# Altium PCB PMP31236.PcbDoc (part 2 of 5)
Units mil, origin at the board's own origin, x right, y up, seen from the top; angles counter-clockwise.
Board outline 6425 x 5322.16 mil, 6 copper layers (Top Layer, Power / GND 1, Signal Layer 1, Signal Layer 2, Power / GND 2, Bottom Layer), stack 78.712 mil thick; 732 components, 346 nets, 1735 pads, 719 vias.
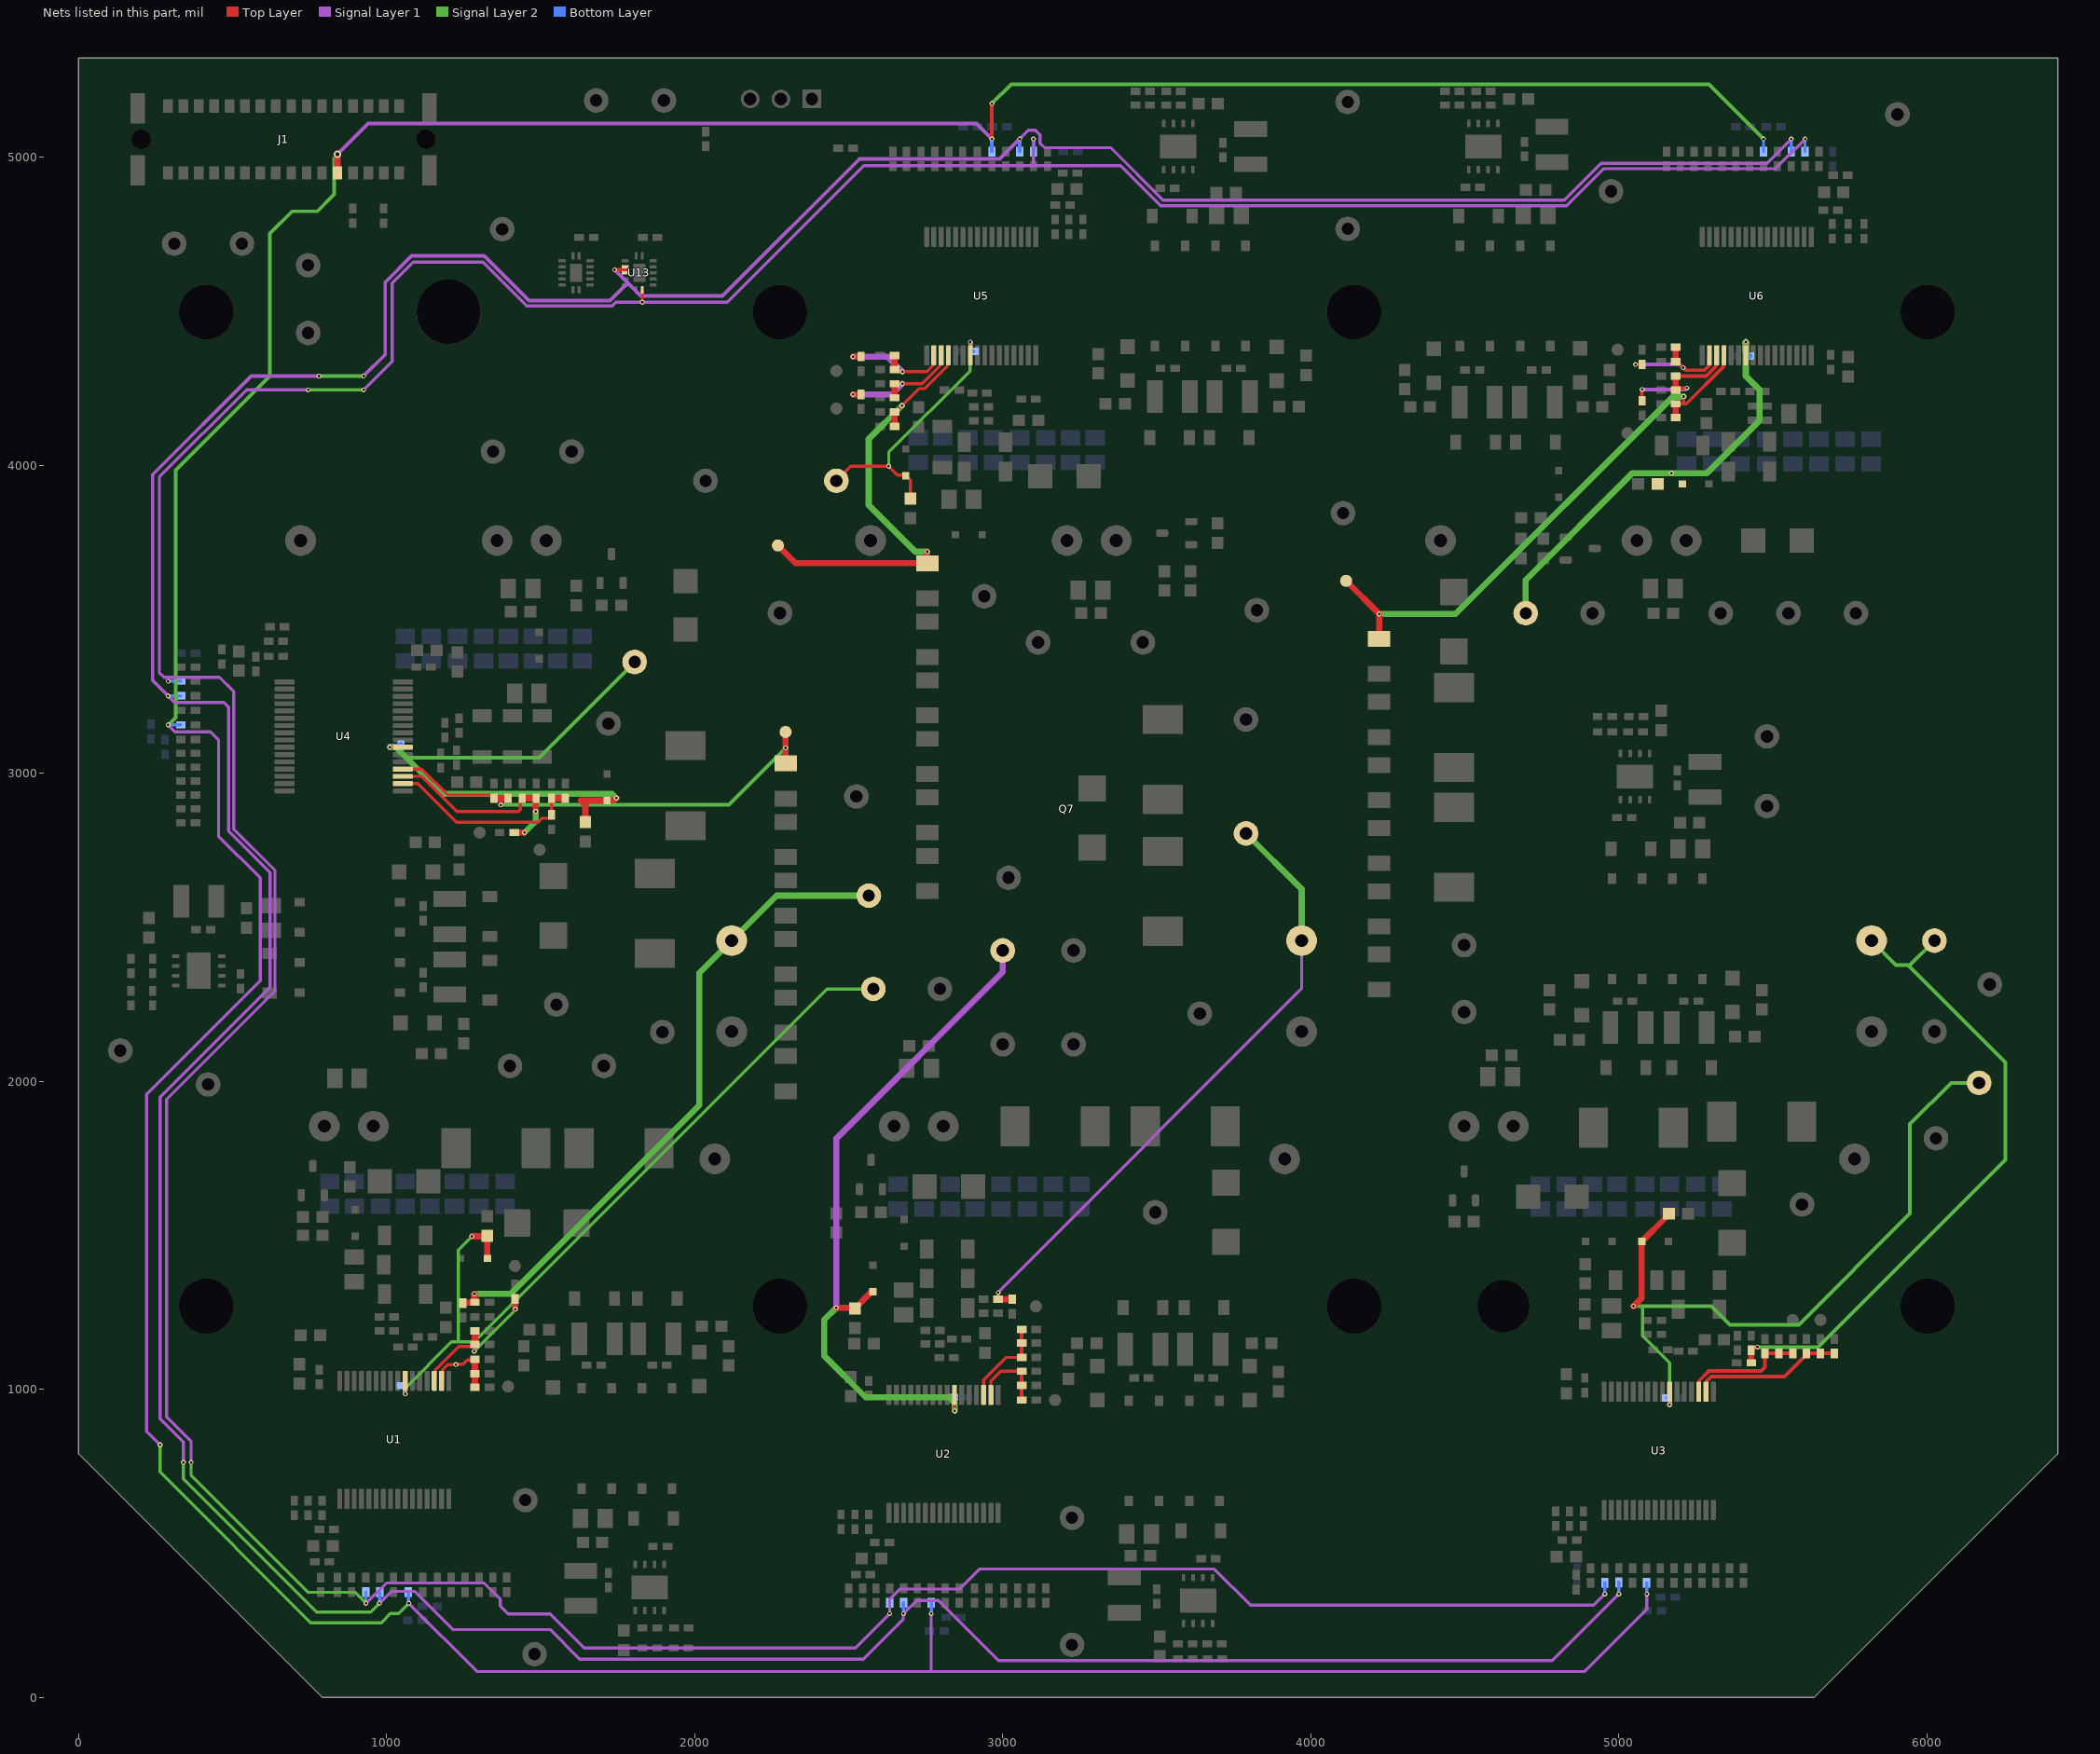
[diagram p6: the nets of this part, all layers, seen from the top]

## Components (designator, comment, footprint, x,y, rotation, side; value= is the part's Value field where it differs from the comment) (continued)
R248 "CRCW0402154KFKED" 0402 1887.81,489.9 r0 top value=154k
R249 "CRCW04020000Z0ED" 0402 1854.47,225 r180 top value=0
R250 "CRCW040215K4FKED" 0402 1955,160 r180 top value=15.4k
R251 "CRCW040212K1FKED" 0402 1956.38,225 r180 top value=12.1k
R252 "CRCW060310R0FKEAHP" 0603 1125,2776.38 r0 top value=10.0
R253 "CRCW08054K70JNEA" 0805_HV 625,2530 r90 top value=4.7k
R254 "CRCW040266K5FKED" 0402 170,2374.37 r90 top value=66.5k
R255 "CRCW060310R0FKEAHP" 0603 1145,2090 r0 top value=10.0
R256 "CRCW0402154KFKED" 0402 525,2325 r270 top value=154k
R257 "CRCW04020000Z0ED" 0402 240,2374.37 r90 top value=0
R258 "CRCW040215K4FKED" 0402 170,2270 r90 top value=15.4k
R259 "CRCW040212K1FKED" 0402 240,2270 r90 top value=12.1k
R260 "CRCW060310R0FKEAHP" 0603 3213.05,1065.12 r90 top value=10.0
R261 "CRCW08054K70JNEA" 0805_HV 3442.3,530.12 r180 top value=4.7k
R262 "CRCW040266K5FKED" 0402 3592.87,125 r180 top value=66.5k
R263 "CRCW060310R0FKEAHP" 0603 3895,1025 r90 top value=10.0
R264 "CRCW0402154KFKED" 0402 3668.38,449.91 r0 top value=154k
R265 "CRCW04020000Z0ED" 0402 3592.87,173.74 r180 top value=0
R266 "CRCW040215K4FKED" 0402 3688.62,125 r180 top value=15.4k
R267 "CRCW040212K1FKED" 0402 3688.05,173.74 r180 top value=12.1k
R268 "CRCW060310R0FKEAHP" 0603 3985,4325 r270 top value=10.0
R269 "CRCW08054K70JNEA" 0805_HV 3735,4815 r0 top value=4.7k
R270 "CRCW040266K5FKED" 0402 3554.25,5215 r0 top value=66.5k
R271 "CRCW060310R0FKEAHP" 0603 3310,4330 r270 top value=10.0
R272 "CRCW0402154KFKED" 0402 3535,4900 r180 top value=154k
R273 "CRCW04020000Z0ED" 0402 3554.25,5170 r0 top value=0
R274 "CRCW040215K4FKED" 0402 3455,5215 r0 top value=15.4k
R275 "CRCW040212K1FKED" 0402 3455,5170 r0 top value=12.1k
R276 "CRCW060310R0FKEAHP" 0603 5465,2265 r270 top value=10.0
R277 "CRCW08054K70JNEA" 0805_HV 5232.01,2755 r0 top value=4.7k
R278 "CRCW040266K5FKED" 0402 5056.38,3185 r0 top value=66.5k
R279 "CRCW060310R0FKEAHP" 0603 4775,2265 r270 top value=10.0
R280 "CRCW0402154KFKED" 0402 5018.33,2856.32 r180 top value=154k
R281 "CRCW04020000Z0ED" 0402 5054.72,3135 r0 top value=0
R282 "CRCW040215K4FKED" 0402 4955,3185 r0 top value=15.4k
R283 "CRCW040212K1FKED" 0402 4955,3135 r0 top value=12.1k
R284 "CRCW060310R0FKEAHP" 0603 4970,4278.5 r270 top value=10.0
R285 "CRCW08054K70JNEA" 0805_HV 4730,4815 r0 top value=4.7k
R286 "CRCW040266K5FKED" 0402 4560.28,5215 r0 top value=66.5k
R287 "CRCW060310R0FKEAHP" 0603 4305,4278.5 r270 top value=10.0
R288 "CRCW0402154KFKED" 0402 4525.53,4903.34 r180 top value=154k
R289 "CRCW04020000Z0ED" 0402 4560.28,5170 r0 top value=0
R290 "CRCW040215K4FKED" 0402 4459.19,5215 r0 top value=15.4k
R291 "CRCW040212K1FKED" 0402 4459.19,5170 r0 top value=12.1k
R292 "CRCW040210K0FKED" 0402 2490,5030 r0 top value=10.0k
R293 "CRCW040210K0FKED" 0402 2035,5060 r90 top value=10.0k
R294 "CRCW040247K0JNED" 0402 889.84,4810 r270 top value=47k
R295 "CRCW040247K0JNED" 0402 990,4810 r90 top value=47k
T1 "YA8916-BL" Coilcraft_YA8916-BL 1779.47,840.75 r90 top value=30uH
T2 "YA8916-BL" Coilcraft_YA8916-BL 880,2435 r0 top value=30uH
T3 "YA8916-BL" Coilcraft_YA8916-BL 3556.64,800.12 r90 top value=30uH
T4 "YA8916-BL" Coilcraft_YA8916-BL 3641.3,4550 r270 top value=30uH
T5 "YA8916-BL" Coilcraft_YA8916-BL 5125,2495 r270 top value=30uH
T6 "YA8916-BL" Coilcraft_YA8916-BL 4630.98,4550 r270 top value=30uH
TP1 "" Keystone5002 1550.78,2248.97 r0 top
TP2 "" Keystone5002 1705,2050 r90 top
TP3 "" Keystone5002 2580,2300 r90 top
TP4 "" Keystone5002 2796.26,2300 r90 top
TP5 "5000" Keystone5000 530,4720 r90 top
TP6 "5000" Keystone5000 1400,2050 r90 top
TP7 "5000" Keystone5000 2565,2602.91 r90 top
TP8 "5001" Keystone5001 1895,2160 r90 top
TP9 "TP_SM_1MM" TP_SM_1MM#1 1394.02,1009.06 r90 top
TP10 "TP_SM_1MM" TP_SM_1MM#1 1416.23,1400.26 r90 top
TP11 "5001" Keystone5001 1375,4766.81 r90 top
TP12 "" Keystone5002 3230,2425 r180 top
TP13 "" Keystone5002 3230,2120 r180 top
TP14 "" Keystone5002 3000,2425 r180 top
TP15 "" Keystone5002 3019,2660.91 r180 top
TP16 "5000" Keystone5000 745,4430 r90 top
TP17 "5000" Keystone5000 3000,2120 r90 top
TP18 "5000" Keystone5000 3790,2805 r90 top
TP19 "5001" Keystone5001 3495.11,1575 r90 top
TP20 "TP_SM_1MM" TP_SM_1MM#1 3170,965 r90 top
TP21 "TP_SM_1MM" TP_SM_1MM#1 3107.91,1269.43 r90 top
TP22 "" Keystone5002 6025,2161.61 r180 top
TP23 "" Keystone5002 5595,1600 r180 top
TP24 "" Keystone5002 6170,1995 r180 top
TP25 "" Keystone5002 6030,1815 r180 top
TP26 "5000" Keystone5000 745,4650 r90 top
TP27 "5000" Keystone5000 4498.03,2224.88 r90 top
TP28 "5000" Keystone5000 6025,2456.89 r90 top
TP29 "5001" Keystone5001 4498.03,2442.17 r90 top
TP30 "TP_SM_1MM" TP_SM_1MM#2 5655,1226.91 r90 top
TP31 "TP_SM_1MM" TP_SM_1MM#3 5565,1230.35 r90 top
TP32 "" Keystone5002 2035,3950 r270 top
TP33 "" Keystone5002 2276.77,3520.91 r270 top
TP34 "" Keystone5002 1805,3361.69 r270 top
TP35 "" Keystone5002 1720,3161.46 r270 top
TP36 "5000" Keystone5000 310,4720 r90 top
TP37 "5000" Keystone5000 1600,4045 r90 top
TP38 "TP_SM_1MM" TP_SM_1MM#1 2295,3134.38 r90 top
TP39 "5000" Keystone5000 2525,2925 r90 top
TP40 "5001" Keystone5001 1345,4045 r90 top
TP41 "TP_SM_1MM" TP_SM_1MM#1 1496.43,2751.93 r90 top
TP42 "TP_SM_1MM" TP_SM_1MM#1 1301.94,2807.83 r90 top
TP43 "" Keystone5002 3825,3530 r90 top
TP44 "" Keystone5002 3790,3174.92 r90 top
TP45 "" Keystone5002 2460,3950 r90 top
TP46 "" Keystone5002 2940,3575 r90 top
TP47 "5000" Keystone5000 1680,5185 r90 top
TP48 "5000" Keystone5000 3455,3425 r90 top
TP49 "TP_SM_1MM" TP_SM_1MM#1 2270,3740 r90 top
TP50 "5000" Keystone5000 3640,2220 r90 top
TP51 "5001" Keystone5001 3115.04,3425 r90 top
TP52 "TP_SM_1MM" TP_SM_1MM#1 2460,4306.73 r90 top
TP53 "TP_SM_1MM" TP_SM_1MM#1 2460,4184.74 r90 top
TP54 "" Keystone5002 5551.18,3520 r90 top
TP55 "" Keystone5002 5770,3520 r90 top
TP56 "" Keystone5002 4697.97,3520 r90 top
TP57 "" Keystone5002 4105,3845 r90 top
TP58 "5000" Keystone5000 1900,5185 r90 top
TP59 "5000" Keystone5000 5331.18,3520 r90 top
TP60 "TP_SM_1MM" TP_SM_1MM#1 4115,3625 r90 top
TP61 "5000" Keystone5000 6205,2315 r90 top
TP62 "5001" Keystone5001 4915,3520 r90 top
TP63 "TP_SM_1MM" TP_SM_1MM#1 4996.23,4375.94 r90 top
TP64 "TP_SM_1MM" TP_SM_1MM#1 5028.05,4104.82 r90 top
TP65 "5000" Keystone5000 1450,640 r0 top
TP66 "5001" Keystone5001 1480,140 r0 top
TP67 "5000" Keystone5000 420,1990 r0 top
TP68 "5001" Keystone5001 135,2100 r0 top
TP69 "5000" Keystone5000 3225,582.52 r0 top
TP70 "5001" Keystone5001 3225,170 r90 top
TP71 "5000" Keystone5000 4120,4767.87 r90 top
TP72 "5001" Keystone5001 4120,5180 r90 top
TP73 "5000" Keystone5000 5481.18,2893.7 r90 top
TP74 "5001" Keystone5001 5481.18,3120 r90 top
TP75 "5000" Keystone5000 4975,4890 r90 top
TP76 "5001" Keystone5001 5905,5140 r90 top
U1 "PUCC5880QDFCRQ1" DFC0032A-MFG 1024.47,835.75 r90 top
U2 "PUCC5880QDFCRQ1" DFC0032A-MFG 2808.05,790.12 r90 top
U3 "PUCC5880QDFCRQ1" DFC0032A-MFG 5130,800.12 r90 top
U4 "PUCC5880QDFCRQ1" DFC0032A-MFG 860,3120 r0 top
U5 "PUCC5880QDFCRQ1" DFC0032A-MFG 2930,4550 r270 top
U6 "PUCC5880QDFCRQ1" DFC0032A-MFG 5447.99,4550 r270 top
U7 "LM5180QNGURQ1" NGU0008C 1853.72,356.93 r270 top
U8 "LM5180QNGURQ1" NGU0008C 390,2358.62 r180 top
U9 "LM5180QNGURQ1" NGU0008C 3634.37,313.94 r270 top
U10 "LM5180QNGURQ1" NGU0008C 3570,5035 r90 top
U11 "LM5180QNGURQ1" NGU0008C 5052.76,2989.8 r90 top
U12 "LM5180QNGURQ1" NGU0008C 4560.28,5035 r90 top
U13 "SN74HCS00BQAR" BQA0014A-MFG 1819.72,4625 r0 top
U14 "SN74HCS00BQAR" BQA0014A-MFG 1614.72,4625 r0 top

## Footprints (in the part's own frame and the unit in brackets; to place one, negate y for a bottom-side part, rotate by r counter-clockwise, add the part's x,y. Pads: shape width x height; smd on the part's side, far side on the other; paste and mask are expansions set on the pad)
0402 [mm] "0402 from SM-752 data"
  rect 0.8x0.6 smd: 1(-0.6,0) 2(0.6,0)
  silkscreen extent -1.22,-0.52 1.22,0.52, body extent -0.55,-0.3 0.55,0.3, height 0.6
0603 [mm] "0603 from SM-752 data"
  rect 1x0.95 smd: 1(-0.8,0) 2(0.8,0)
  silkscreen extent -1.52,-0.69 1.52,0.69, body extent -0.87,-0.47 0.87,0.47, height 1
0805_HV [mil] "0805 with 30mil clearance between pads"
  rect 50x63 smd: 1(-40,0) 2(40,0)
  silkscreen extent -74,-40 74,40, body extent -43,-29 43,29, height 57
1206 [mm] "1206 from SM-752 data"
  rect 1.3x1.85 smd: 1(-1.45,0) 2(1.45,0)
  silkscreen extent -2.4,-1.21 2.4,1.21, body extent -1.7,-0.9 1.7,0.9, height 1.35
1206_190 [mm] "1206_190"
  rect 1.1x1.6 smd: 1(-1.7,0) 2(1.7,0)
  silkscreen extent -0.9,-1 0.9,1, body extent -1.75,-0.95 1.75,0.95, height 1.9
1210_270 [mm] "1210"
  rect 1.3x2.7 smd: 1(-1.45,0) 2(1.45,0)
  silkscreen extent -2.32,-1.57 2.32,1.57, body extent -1.7,-1.35 1.7,1.35, height 2.7
BQA0014A-MFG [mm]
  rrect40% 0.25x0.6 smd paste+0 mask+0: 1(-0.25,1.4) 7(-0.25,-1.4) 8(0.25,-1.4) 14(0.25,1.4)
  rrect40% 0.6x0.25 smd paste+0 mask+0: 2(-1.15,1) 3(-1.15,0.5) 4(-1.15,0) 5(-1.15,-0.5) 6(-1.15,-1) 9(1.15,-1) 10(1.15,-0.5) 11(1.15,0) 12(1.15,0.5) 13(1.15,1)
  rrect10% 1x1.5 smd paste-1000 mask+0: 15(0,0)
  silkscreen extent -1.3,-1.55 1.3,2.37, body extent -1.55,-1.8 1.55,1.8, height 0.25
Coilcraft_YA8916-BL [mm] "SMD, 8-Leads, Body 9.3x10.2mm, Pitch 2.49mm"
  rrect14% 0.87x0.71 smd: 1(-4.135,3.735) 2(-4.135,1.245) 3(-4.135,-1.245) 4(-4.135,-3.735) 5(4.135,-3.735) 6(4.135,-1.245) 7(4.135,1.245) 8(4.135,3.735)
  body extent -4.65,-5.1 4.65,5.1, height 10.6
DFC0032A-MFG [mm]
  rrect24% 1.65x0.41 smd paste+0 mask+0: 1(-4.875,4.5) 2(-4.875,3.9) 3(-4.875,3.3) 4(-4.875,2.7) 5(-4.875,2.1) 6(-4.875,1.5) 7(-4.875,0.9) 8(-4.875,0.3) 9(-4.875,-0.3) 10(-4.875,-0.9) 11(-4.875,-1.5) 12(-4.875,-2.1) 13(-4.875,-2.7) 14(-4.875,-3.3) 15(-4.875,-3.9) 16(-4.875,-4.5) 17(4.875,-4.5) 18(4.875,-3.9) 19(4.875,-3.3) 20(4.875,-2.7) 21(4.875,-2.1) 22(4.875,-1.5) 23(4.875,-0.9) 24(4.875,-0.3) 25(4.875,0.3) 26(4.875,0.9) 27(4.875,1.5) 28(4.875,2.1) 29(4.875,2.7) 30(4.875,3.3) 31(4.875,3.9) 32(4.875,4.5)
  silkscreen extent -6.52,-5.25 3.8,5.25, body extent -5.15,-5.15 5.15,5.15, height 2.65
FP-1.5SMC530A_SMC-MFG [mm]
  rrect4% 2.4x3.3 smd paste+0 mask+0: 1(-3.3,0) 2(3.3,0)
  silkscreen extent -5.2,-3.11 3.55,3.11, body extent -3.97,-2.95 3.97,2.95, height 2.62
FP-0405-0-15-15-34-27-04-0_HDR1-MFG [mil]
  round 100 hole 36 paste-39370.1 mask+0: 1(0,0)
  silkscreen extent -68,-68 68,68, body extent -45,-45 45,45, height 256
FP-254589_CONN_HDR32-MFG [mm]
  rrect8% 1.2x2.5 smd paste+0 mask+0: 1(-12.035,2.55) 2(12.035,2.55) 3(-12.035,-2.55) 4(12.035,-2.55)
  rrect13% 0.8x1.1 smd paste+0 mask+0: a1(9.525,-2.75) a2(8.255,-2.75) a3(6.985,-2.75) a4(5.715,-2.75) a5(4.445,-2.75) a6(3.175,-2.75) a7(1.905,-2.75) a8(0.635,-2.75) a9(-0.635,-2.75) a10(-1.905,-2.75) a11(-3.175,-2.75) a12(-4.445,-2.75) a13(-5.715,-2.75) a14(-6.985,-2.75) a15(-8.255,-2.75) a16(-9.525,-2.75) b1(9.525,2.75) b2(8.255,2.75) b3(6.985,2.75) b4(5.715,2.75) b5(4.445,2.75) b6(3.175,2.75) b7(1.905,2.75) b8(0.635,2.75) b9(-0.635,2.75) b10(-1.905,2.75) b11(-3.175,2.75) b12(-4.445,2.75) b13(-5.715,2.75) b14(-6.985,2.75) b15(-8.255,2.75) b16(-9.525,2.75)
  round 1.6 hole 1.6 unplated paste-1000 mask+0: ""(-11.735,0) ""(11.735,0)
  silkscreen extent -11.06,-3.97 11.06,2.1, body extent -12.8,-3.9 12.8,3.9, height 0.25
FP-FS660R08A6P2FBBPSA1_PTH_MD_1554MM5_100MM5-MFG [mm]
  rrect6% 1.66x1.66 hole 1.06 paste-1000 mask+0: C1(-29.05,29.35)
  round 1.66 hole 1.06 paste-1000 mask+0: C2(-63.2,-21.65) C3(17.95,29.35) C4(-16.2,-21.65) C5(64.95,29.35) C6(30.8,-21.65) E1(-57.2,26.65) E2(-47,-21.65) E3(-10.2,26.65) E4(0,-21.65) E5(36.8,26.65) E6(47,-21.65) G1(-61.25,26.65) G2(-42.95,-21.65) G3(-14.25,26.65) G4(4.05,-21.65) G5(32.75,26.65) G6(51.05,-21.65) T1(-27.65,11.35) T2(-27.65,18.85) T3(19.35,11.35) T4(19.35,18.85) T5(66.35,11.35) T6(66.35,18.85)
  round 4.5 hole 4.5 unplated paste-1000 mask+0: ""(-71,-40.5) ""(-71,41.5) ""(-23.67,-40.5) ""(-23.67,41.5) ""(23.67,-40.5) ""(23.67,41.5) ""(71,-40.5) ""(71,41.5)
  round 5.3 hole 5.3 unplated paste-1000 mask+0: ""(-51,-40.5)
  round 4.3 hole 4.3 unplated paste-1000 mask+0: ""(36,41.5)
  silkscreen extent -77.65,-50.65 77.65,51.27, body extent -77.25,-62.75 77.25,63.75, height 23.31
FP-GB02SLT12-214_DO-214AA-MFG [mm]
  rrect5% 2.16x2.26 smd paste+0 mask+0: 1(-2.45,0) 2(2.45,0)
  silkscreen extent -4.3,-1.97 2.28,1.97, body extent -2.7,-1.81 2.7,1.81, height 2.44
Keystone5000 [mil] "For Keystone 500x miniature loop terminals"
  round 80 hole 40: 1(0,0)
  silkscreen extent -52,-52 52,52, body extent -49,-49 49,49, height 182
Keystone5001 [mil] "For Keystone 500x miniature loop terminals"
  round 80 hole 40: 1(0,0)
  silkscreen extent -52,-52 52,52, body extent -49,-49 49,49, height 182
Keystone5002 [mil] "For Keystone 500x miniature loop terminals"
  round 80 hole 40: 1(0,0)
  silkscreen extent -52,-52 52,52, body extent -49,-49 49,49, height 182
NGU0008C [mm] "SON, 8-Leads, Body 4x4mm, Pitch 0.8mm"
  rrect33% 0.6x0.3 smd: 1(-1.9,1.2) 2(-1.9,0.4) 3(-1.9,-0.4) 4(-1.9,-1.2) 5(1.9,-1.2) 6(1.9,-0.4) 7(1.9,0.4) 8(1.9,1.2)
  rrect8% 1.75x1.31 on Top Paste: 9(0,0.755) 9(0,-0.755)
  rrect5% 1.98x3 smd paste-1.5: 9(0,0)
  silkscreen extent -2.15,-2.15 2.15,2.15, body extent -2,-2 2,2, height 0.77
Samtec_HTSW-103-09-x-S [mm] "Header, 3x1, 2.54mm, TH"
  rect 1.55x1.55 hole 1.02: 1(-2.54,0)
  round 1.55 hole 1.02: 2(0,0) 3(2.54,0)
  silkscreen extent -3.81,-1.24 3.81,1.5, body extent -3.81,-1.24 3.81,1.24, height 8.38
SMA [mm] "Molded Diode, 2-Leads, Body 4.3x2.6mm, IPC Medium Density, based on OnSemi component dimensions and land pattern"
  rect 2x2 smd: 1(-2,0) 2(2,0)
  silkscreen extent -3.66,-1.57 2.79,1.57, body extent -2.6,-1.3 2.6,1.3, height 2.42
SOD-123 [mm] "On Semi recommended land pattern"
  rect 0.915x1.22 smd: 1(-1.637,0) 2(1.637,0)
  silkscreen extent -2.74,-1.17 2.03,1.17, body extent -1.93,-0.9 1.93,0.9, height 1.35
SOD-123F [mm] "NXP recommended land pattern"
  rect 1.2x1.2 smd paste-0.05: 1(-1.4,0) 2(1.4,0)
  silkscreen extent -2.64,-1.12 2.01,1.12, body extent -1.8,-0.85 1.8,0.85, height 1.2
SOD-323 [mm] "NXP recommended land pattern"
  rect 0.6x0.6 smd paste-0.05: 1(-1.1,0) 2(1.1,0)
  silkscreen extent -2.06,-0.86 1.53,0.86, body extent -1.3,-0.67 1.3,0.68, height 1.1
SOT-23 [mm] "SOT23, 3-Leads, Body 2.9x1.3mm, Pitch 0.95mm, Lead Span 2.5mm, IPC Medium Density"
  rrect50% 1x0.6 smd: 1(-1.2,0.95) 2(-1.2,-0.95) 3(1.2,0)
  silkscreen extent -1.62,-1.5 0.7,1.5, body extent -1.16,-1.45 1.21,1.45, height 1
TP_SM_1MM#1 [mm] "1mm Test Point, SMT"
  round 1 smd paste-0.5: 1(0,0)
TP_SM_1MM#2 [mm] "1mm Test Point, SMT"
  round 1 smd paste-0.5: 1(-0.049,0)
TP_SM_1MM#3 [mm] "1mm Test Point, SMT"
  round 1 smd paste-0.5: 1(-0.136,0)

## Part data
C1 C31 C61 C91 C121 C151: library part CMP-0007067-4, "CAP, CERM, 1 uF, 35 V, +/- 10%, X7R, AEC-Q200 Grade 1, 0603", Cap_Case=0603, Manufacturer=TDK, PartNumber=CGA3E1X7R1V105K080AC, Supplier Part Number 1=445-174215-1-ND, TempCo=X7R, Tolerance_%=10%, Value1="0.005522 ohm", Value2=35V, ValueDisplayed=1uF
C2 C9 C25 C26 C29 C32 C39 C55 C56 C59 C62 C69 C85 C86 C89 C92 C99 C102 C115 C116 C119 C122 C129 C132 C145 C146 C149 C152 C159 C162 C175 C176 C179: library part CMP-0006356-2, "CAP, CERM, 0.1 uF, 50 V, +/- 10%, X7R, AEC-Q200 Grade 1, 0402", Cap_Case=0402, Manufacturer=MuRata, Supplier Part Number 1=490-10672-1-ND, TempCo=X7R, Tolerance_%=10%, Value1=Unknown, Value2=50V, ValueDisplayed=0.1uF
C3 C4 C5 C6 C7 C13 C14 C19 C20 C21 C22 C23 C33 C34 C35 C36 C37 C43 C44 C49 C50 C51 C52 C53 C63 C64 C65 C66 C67 C73 C74 C79 C80 C81 C82 C83 C93 C94 C95 C96 C97 C103 C104 C109 C110 C111 C112 C113 C123 C124 C125 C126 C127 C133 C134 C139 C140 C141 C142 C143 C153 C154 C155 C156 C157 C163 C164 C169 C170 C171 C172 C173: library part CMP-0006410-2, "CAP, CERM, 100 pF, 50 V, +/- 5%, C0G/NP0, 0402", Cap_Case=0402, Manufacturer=MuRata, Supplier Part Number 1=81-GRM1555C1H101JA1D, TempCo=C0G/NP0, Tolerance_%=5%, Value1=Unknown, Value2=50V, ValueDisplayed=100pF
C8 C12 C38 C42 C68 C72 C98 C128 C158: library part CMP-0006324-2, "CAP, CERM, 0.01 uF, 50 V, +/- 10%, X7R, AEC-Q200 Grade 1, 0402", Cap_Case=0402, Manufacturer=TDK, Supplier Part Number 1=445-6893-1-ND, TempCo=X7R, Tolerance_%=10%, Value1="0.333065 ohm", Value2=50V, ValueDisplayed=0.01uF
C10 C40 C70 C100 C130 C160: library part CMP-0007067-4, "CAP, CERM, 1 uF, 35 V, +/- 10%, X7R, AEC-Q200 Grade 1, 0603", Cap_Case=0603, Manufacturer=TDK, Supplier Part Number 1=445-174215-1-ND, TempCo=X7R, Tolerance_%=10%, Value1="0.005522 ohm", Value2=35V, ValueDisplayed=1uF
C11 C41 C71 C101 C131 C161: library part CMP-0007725-2, "CAP, CERM, 0.1 uF, 50 V, +/- 10%, X7R, AEC-Q200 Grade 0, 0805", Cap_Case=0805, Manufacturer=Kemet, Supplier Part Number 1=399-6928-1-ND, TempCo=X7R, Tolerance_%=10%, Value1=Unknown, Value2=50V, ValueDisplayed=0.1uF
C15 C16 C17 C18 C45 C46 C47 C48 C75 C76 C77 C78 C105 C106 C107 C108 C135 C136 C137 C138 C165 C166 C167 C168: library part CMP-0860290-1, "CAP, CERM, 10 pF, 50 V,+/- 5%, C0G/NP0, AEC-Q200 Grade 1, 0402", Cap_Case=0402, Manufacturer=MuRata, TempCo=C0G/NP0, Tolerance_%=5%, Value2=50V, ValueDisplayed=10pF
C24 C28 C30 C54 C58 C60 C84 C88 C90 C114 C118 C120 C144 C148 C150 C174 C178 C180: library part CMP-0008772-2, "CAP, CERM, 10 uF, 35 V, +/- 10%, X7R, AEC-Q200 Grade 1, 1206_190", Cap_Case=1206_190, Manufacturer=TDK, PartNumber=CGA5L1X7R1V106K160AC, Supplier Part Number 1=445-174428-1-ND, TempCo=X7R, Tolerance_%=10%, Value1="0.002229 ohm", Value2=35V, ValueDisplayed=10uF
C27 C57 C87 C117 C147 C177: library part CMP-0007977-2, "CAP, CERM, 2.2 uF, 50 V, +/- 10%, X7R, AEC-Q200 Grade 1, 0805", Cap_Case=0805, Manufacturer=TDK, Supplier Part Number 1=445-174216-1-ND, TempCo=X7R, Tolerance_%=10%, Value1="0.003288 ohm", Value2=50V, ValueDisplayed=2.2uF
C181 C189 C191 C199 C201 C209 C211 C219 C221 C229 C231 C239: library part CMP-0007432-5, "CAP, CERM, 1000 pF, 50 V, +/- 10%, X7R, 0603", Cap_Case=0603, Manufacturer=MuRata, Supplier Part Number 1=490-1494-1-ND, TempCo=X7R, Tolerance_%=10%, Value1=Unknown, Value2=50V, ValueDisplayed=1000pF
C182 C185 C187 C192 C195 C197 C202 C205 C207 C212 C215 C217 C222 C225 C227 C232 C235 C237: library part CMP-0006675-2, "CAP, CERM, 0.1 uF, 50 V, +/- 20%, X7R, 0402", Cap_Case=0402, Manufacturer=MuRata, Supplier Part Number 1=490-10701-1-ND, TempCo=X7R, Tolerance_%=20%, Value1=Unknown, Value2=50V, ValueDisplayed=0.1uF
C183 C188 C193 C198 C203 C208 C213 C218 C223 C228 C233 C238: library part CMP-0009255-2, "CAP, CERM, 22 uF, 25 V, +/- 10%, X7R, AEC-Q200 Grade 1, 1210", Cap_Case=1210, Manufacturer="Taiyo Yuden", TempCo=X7R, Tolerance_%=10%, Value1=Unknown, Value2=25V, ValueDisplayed=22uF
C184 C194 C204 C214 C224 C234: library part CMP-0009226-3, "CAP, CERM, 10 uF, 50 V, +/- 10%, X7R, 1210", Cap_Case=1210, Manufacturer=MuRata, Supplier Part Number 1=490-6544-1-ND, TempCo=X7R, Tolerance_%=10%, Value1=Unknown, Value2=50V, ValueDisplayed=10uF
C186 C196 C206 C216 C226 C236: library part CMP-0007487-4, "CAP, CERM, 6800 pF, 100 V, +/- 10%, X7R, 0603", Cap_Case=0603, Manufacturer=MuRata, Supplier Part Number 1=GRM188R72A682KA01D-ND, TempCo=X7R, Tolerance_%=10%, Value1=Unknown, Value2=100V, ValueDisplayed=6800pF
C190 C200 C210 C220 C230 C240: library part CMP-0007444-4, "CAP, CERM, 0.022 uF, 50 V, +/- 10%, X7R, 0603", Cap_Case=0603, Manufacturer=MuRata, Supplier Part Number 1=490-1517-1-ND, TempCo=X7R, Tolerance_%=10%, Value1=Unknown, Value2=50V, ValueDisplayed=0.022uF
C241 C242: library part CMP-0006659-2, "CAP, CERM, 0.1 uF, 25 V, +/- 10%, X7R, 0402", Cap_Case=0402, Manufacturer=MuRata, Supplier Part Number 1=490-10698-1-ND, TempCo=X7R, Tolerance_%=10%, Value1=Unknown, Value2=25V, ValueDisplayed=0.1uF
D1 D7 D13 D19 D25 D31: library part CMP-0095009-1, "Diode Silicon Carbide Schottky 1200 V 2A (DC) Surface Mount DO-214AA", Digikey Part Number=1242-1170-1-ND, Forward Current=2A, Manufacturer="GeneSiC Semiconductor", Max Surge Forward Current=20A, Mouser Part Number=905-GB02SLT12-214, Operating Temperature Range="-55°C to +175°C", Peak Reverse Current=1uA, ValueDisplayed=122pF
D2 D6 D8 D12 D14 D18 D20 D24 D26 D30 D32 D36: library part CMP-0028458-1, "Diode, Schottky, 30 V, 0.2 A, SOD-323", Manufacturer="Diodes Inc.", Supplier Part Number 1=BAT54WS-FDICT-ND, Value1=0.2A, Value2=0.7V
D3 D4 D9 D10 D15 D16 D21 D22 D27 D28 D33 D34: library part CMP-0095023-1, "725V Clamp 2.1A Ipp Tvs Diode Surface Mount DO-214AB (SMCJ)", Breakdown Voltage=503.5V, Clamping Voltage=725V, Digikey Part Number=18-1.5SMC530ACT-ND, Manufacturer="Littelfuse Inc", Mouser Part Number=576-1.5SMC530A, Operating Temperature Range="-65°C to +150°C"
D5 D11 D17 D23 D29 D35: library part CMP-0028553-2, "Diode, Schottky, 40 V, 3 A, SMA", Manufacturer="ON Semiconductor", Value1=3A, Value2=0.415V
D37 D41 D42 D46 D47 D51 D52 D56 D57 D61 D62 D66: library part CMP-0028377-2, "Diode, Schottky, 60 V, 1 A, SOD-123F", Manufacturer=Nexperia, Value1=1A, Value2=0.57V
D38 D43 D48 D53 D58 D63: library part CMP-0005755-1, "Diode, Zener, 18 V, 500 mW, SOD-123", Manufacturer="Diodes Inc.", Power_W=500mW, Supplier Part Number 1=MMSZ5248B-FDICT-ND, Value1=0.5W
D39 D44 D49 D54 D59 D64: library part CMP-0080761-1, "Diode, Switching, 100 V, 0.25 A, AEC-Q101, SOD-123", Manufacturer=Vishay-Semiconductor, Supplier Part Number 1=BAS16D-E3-08GICT-ND, Value1=0.25A, Value2=1.25V
D40 D45 D50 D55 D60 D65: library part CMP-0077567-2, "Diode, Zener, 8.2 V, 500 mW, AEC-Q101, SOD-123", Manufacturer=Vishay-Semiconductor, Power_W=500mW, Value1=0.5W
J1: library part CMP-0098102-2, Current_A=1.7A, Digikey Part Number=2684-254589CT-ND, Manufacturer="TE Connectivity Erni", Mouser Part Number=305-254589, Operating Temperature Range="-55°C to +125°C"
J2: library part CMP-0075627-1, "Header, 100mil, 3x1, Gold, TH", Color=Black, Manufacturer=Samtec
J3 J4 J5 J6 J7 J8 J9 J10 J11 J12 J13 J14 J15 J16 J17 J18 J19 J20 J21 J22 J23 J24 J25 J26: library part CMP-0087418-2, "CONN PIN RCPT .032-.046 PRESSFIT", Current_A=8A, Manufacturer=Mill-Max
Q1 Q2 Q3 Q4 Q5 Q6: library part CMP-0000739-1, "MOSFET, N-CH, 40 V, 5.6 A, SOT-23", Alternate Manufacturer=None, Manufacturer=Vishay-Siliconix, Supplier Part Number 1=SI2318CDS-T1-GE3CT-ND, Value1=0.05, Value2="5.8 nC"
Q7: library part CMP-0098118-1, "IGBT Module Trench Field Stop Three Phase Inverter 750 V 450 A 1053 W Chassis Mount AG-HYBRIDD-1", Collector Current=450A, Digikey Part Number=448-FS660R08A6P2FBBPSA1-ND, Manufacturer=Infineon, Mouser Part Number=726-FS660R08A6P2FBBP, Operating Temperature Range="-40°C to +150°C", Power_W=1053W
R1 R39 R77 R115 R158 R201: library part CMP-0026827-3, "RES, 10, 5%, 0.063 W, AEC-Q200 Grade 0, 0402", Manufacturer=Vishay-Dale, Power_W=63mW, Supplier Part Number 1=541-10JCT-ND, TempCo="200 ppm/C", Tolerance_%=5%, Value2=0.063W, Value_Code=10R0, ValueDisplayed=10
R2 R3 R40 R41 R78 R79 R116 R117 R159 R160 R202 R203 R294: library part CMP-0026935-3, "RES, 47 k, 5%, 0.063 W, AEC-Q200 Grade 0, 0402", Manufacturer=Vishay-Dale, Power_W=63mW, Supplier Part Number 1=541-47KJCT-ND, TempCo="200 ppm/C", Tolerance_%=5%, Value2=0.063W, Value_Code=47k0, ValueDisplayed=47k
R4 R42 R80 R118 R161 R204: library part CMP-0022109-5, "RES, 1.00 k, 1%, 0.1 W, AEC-Q200 Grade 0, 0603", Manufacturer=Vishay-Dale, Power_W=100mW, Supplier Part Number 1=541-1.00KHCT-ND, TempCo="100 ppm/C", Tolerance_%=1%, Value2=0.1W, Value_Code=1k00, ValueDisplayed=1.00k
R5 R7 R8 R11 R14 R15 R18 R22 R26 R28 R31 R34 R35 R43 R45 R46 R49 R52 R53 R56 R60 R64 R66 R69 R72 R73 R81 R83 R84 R87 R90 R91 R94 R98 R102 R104 R107 R110 R111 R119 R121 R122 R125 R128 R129 R130 R134 R140 R142 R145 R147 R148 R162 R164 R165 R168 R171 R172 R173 R177 R183 R185 R188 R190 R191 R205 R207 R208 R211 R214 R215 R216 R220 R226 R228 R231 R233 R234: library part CMP-0026824-2, "RES, 100, 5%, 0.063 W, 0402", Manufacturer=Vishay-Dale, Power_W=63mW, Supplier Part Number 1=541-100JCT-ND, TempCo="200 ppm/C", Tolerance_%=5%, Value2=0.063W, Value_Code=100R, ValueDisplayed=100
R6 R44 R82 R120 R163 R206: library part CMP-0025787-4, "RES, 33, 5%, 0.1 W, AEC-Q200 Grade 0, 0603", Manufacturer=Vishay-Dale, Power_W=100mW, Supplier Part Number 1=541-33GCT-ND, TempCo="200 ppm/C", Tolerance_%=5%, Value2=0.1W, Value_Code=33R0, ValueDisplayed=33
R9 R10 R47 R48 R85 R86 R123 R124 R166 R167 R209 R210: library part CMP-0020847-3, "RES, 10.0, 1%, 0.125 W, AEC-Q200 Grade 0, 0805", Manufacturer=Vishay-Dale, Power_W=125mW, Supplier Part Number 1=541-10.0CCT-ND, TempCo="100 ppm/C", Tolerance_%=1%, Value2=0.125W, Value_Code=10R0, ValueDisplayed=10.0
R12 R13 R50 R51 R88 R89 R126 R127 R169 R170 R212 R213: library part CMP-0021481-3, "RES, 8.45, 1%, 0.125 W, AEC-Q200 Grade 0, 0805", Manufacturer=Vishay-Dale, Power_W=125mW, Supplier Part Number 1=541-8.45CCCT-ND, TempCo="100 ppm/C", Tolerance_%=1%, Value2=0.125W, Value_Code=8R45, ValueDisplayed=8.45
R16 R17 R54 R55 R92 R93 R132 R133 R175 R176 R218 R219: library part CMP-0021044-3, "RES, 20.0, 1%, 0.125 W, AEC-Q200 Grade 0, 0805", Manufacturer=Vishay-Dale, Power_W=125mW, Supplier Part Number 1=541-20.0CCT-ND, TempCo="100 ppm/C", Tolerance_%=1%, Value2=0.125W, Value_Code=20R0, ValueDisplayed=20.0
R19 R57 R95 R131 R174 R217: library part CMP-0025958-3, "RES, 10.0 k, 1%, 0.063 W, AEC-Q200 Grade 0, 0402", Manufacturer=Vishay-Dale, Power_W=63mW, Supplier Part Number 1=541-10.0KLCT-ND, TempCo="100 ppm/C", Tolerance_%=1%, Value2=0.063W, Value_Code=10k0, ValueDisplayed=DNP
R20 R23 R58 R61 R96 R99 R135 R137 R178 R180 R221 R223: library part CMP-0020941-3, "RES, 18.2, 1%, 0.125 W, AEC-Q200 Grade 0, 0805", Manufacturer=Vishay-Dale, Power_W=125mW, Supplier Part Number 1=541-18.2CCT-ND, TempCo="100 ppm/C", Tolerance_%=1%, Value2=0.125W, Value_Code=18R2, ValueDisplayed=18.2
R21 R24 R59 R62 R97 R100 R136 R139 R179 R182 R222 R225: library part CMP-0025697-4, "RES, 0, 5%, 0.1 W, AEC-Q200 Grade 0, 0603", Manufacturer=Vishay-Dale, Power_W=100mW, Supplier Part Number 1=541-0.0GCT-ND, TempCo="200 ppm/C", Tolerance_%=5%, Value2=0.1W, Value_Code=0000, ValueDisplayed=0
R25 R27 R63 R65 R101 R103 R138 R141 R181 R184 R224 R227: library part CMP-0025701-4, "RES, 10 k, 5%, 0.1 W, AEC-Q200 Grade 0, 0603", Manufacturer=Vishay-Dale, Power_W=100mW, Supplier Part Number 1=541-10KGCT-ND, TempCo="200 ppm/C", Tolerance_%=5%, Value2=0.1W, Value_Code=10k0, ValueDisplayed=10k
R29 R32 R67 R70 R105 R108 R143 R146 R186 R189 R229 R232: library part CMP-0025951-3, "RES, 100, 1%, 0.063 W, AEC-Q200 Grade 0, 0402", Manufacturer=Vishay-Dale, Power_W=63mW, Supplier Part Number 1=541-100LCT-ND, TempCo="100 ppm/C", Tolerance_%=1%, Value2=0.063W, Value_Code=100R, ValueDisplayed=100
R30 R37 R38 R68 R75 R76 R106 R113 R114 R144 R149 R150 R187 R192 R193 R230 R235 R236 R292 R293: library part CMP-0025958-3, "RES, 10.0 k, 1%, 0.063 W, AEC-Q200 Grade 0, 0402", Manufacturer=Vishay-Dale, Power_W=63mW, Supplier Part Number 1=541-10.0KLCT-ND, TempCo="100 ppm/C", Tolerance_%=1%, Value2=0.063W, Value_Code=10k0, ValueDisplayed=10.0k
R33 R71 R109: library part CMP-0026822-3, "RES, 0, 5%, 0.063 W, AEC-Q200 Grade 0, 0402", Manufacturer=Vishay-Dale, Power_W=63mW, Supplier Part Number 1=541-0.0JCT-ND, TempCo="200 ppm/C", Tolerance_%=5%, Value2=0.063W, Value_Code=0000, ValueDisplayed=0
R36 R74 R112: library part CMP-0026512-2, "RES, 6.04 k, 1%, 0.063 W, AEC-Q200 Grade 0, 0402", Manufacturer=Vishay-Dale, Power_W=63mW, Supplier Part Number 1=541-6.04KLCT-ND, TempCo="100 ppm/C", Tolerance_%=1%, Value2=0.063W, Value_Code=6k04, ValueDisplayed=6.04k
R151 R152 R153 R154 R155 R156 R194 R195 R196 R197 R198 R199 R237 R238 R239 R240 R241 R242: library part CMP-0016679-3, "RES, 191 k, 1%, 0.25 W, AEC-Q200 Grade 0, 1206", Manufacturer=Vishay-Dale, Power_W=250mW, Supplier Part Number 1=541-191KFCT-ND, TempCo="100 ppm/C", Tolerance_%=1%, Value2=0.25W, Value_Code=191k
R157 R200 R243: library part CMP-0026339-2, "RES, 3.83 k, 1%, 0.063 W, AEC-Q200 Grade 0, 0402", Manufacturer=Vishay-Dale, Power_W=63mW, Supplier Part Number 1=541-3.83KLCT-ND, TempCo="100 ppm/C", Tolerance_%=1%, Value2=0.063W, Value_Code=3k83, ValueDisplayed=3.83k
R244 R247 R252 R255 R260 R263 R268 R271 R276 R279 R284 R287: library part CMP-0022004-4, "RES, 10.0, 1%, 0.25 W, AEC-Q200 Grade 0, 0603", Manufacturer=Vishay-Dale, Power_W=250mW, Supplier Part Number 1=541-10.0SCT-ND, TempCo="100 ppm/C", Tolerance_%=1%, Value2=0.25W, Value_Code=10R0, ValueDisplayed=DNP
R245 R253 R261 R269 R277 R285: library part CMP-0020559-3, "RES, 4.7 k, 5%, 0.125 W, AEC-Q200 Grade 0, 0805", Manufacturer=Vishay-Dale, Power_W=125mW, Supplier Part Number 1=541-4.7KACT-ND, TempCo="200 ppm/C", Tolerance_%=5%, Value2=0.125W, Value_Code=4k70, ValueDisplayed=4.7k
R246 R254 R262 R270 R278 R286: library part CMP-0026502-2, "RES, 66.5 k, 1%, 0.063 W, AEC-Q200 Grade 0, 0402", Manufacturer=Vishay-Dale, Power_W=63mW, Supplier Part Number 1=541-66.5KLCT-ND, TempCo="100 ppm/C", Tolerance_%=1%, Value2=0.063W, Value_Code=66k5, ValueDisplayed=66.5k
R248 R256 R264 R272 R280 R288: library part CMP-0026023-3, "RES, 154 k, 1%, 0.063 W, AEC-Q200 Grade 0, 0402", Manufacturer=Vishay-Dale, Power_W=63mW, Supplier Part Number 1=541-154KLCT-ND, TempCo="100 ppm/C", Tolerance_%=1%, Value2=0.063W, Value_Code=154k
R249 R257 R265 R273 R281 R289: library part CMP-0026822-3, "RES, 0, 5%, 0.063 W, AEC-Q200 Grade 0, 0402", Manufacturer=Vishay-Dale, Power_W=63mW, Supplier Part Number 1=541-0.0JCT-ND, TempCo="200 ppm/C", Tolerance_%=5%, Value2=0.063W, Value_Code=0000, ValueDisplayed=DNP
R250 R258 R266 R274 R282 R290: library part CMP-0026028-3, "RES, 15.4 k, 1%, 0.063 W, AEC-Q200 Grade 0, 0402", Manufacturer=Vishay-Dale, Power_W=63mW, Supplier Part Number 1=541-15.4KLCT-ND, TempCo="100 ppm/C", Tolerance_%=1%, Value2=0.063W, Value_Code=15k4, ValueDisplayed=15.4k
R251 R259 R267 R275 R283 R291: library part CMP-0025991-3, "RES, 12.1 k, 1%, 0.063 W, AEC-Q200 Grade 0, 0402", Manufacturer=Vishay-Dale, Power_W=63mW, Supplier Part Number 1=541-12.1KLCT-ND, TempCo="100 ppm/C", Tolerance_%=1%, Value2=0.063W, Value_Code=12k1, ValueDisplayed=12.1k
R295: library part CMP-0026935-3, "RES, 47 k, 5%, 0.063 W, AEC-Q200 Grade 0, 0402", Manufacturer=Vishay-Dale, Power_W=63mW, Supplier Part Number 1=541-47KJCT-ND, TempCo="200 ppm/C", Tolerance_%=5%, Value2=0.063W, Value_Code=47k0, ValueDisplayed=DNP
T1 T2 T3 T4 T5 T6: library part CMP-0083973-1, "Transformer, 30 uH, SMT", Manufacturer=Coilcraft, ValueDisplayed=30µH
TP1 TP2 TP3 TP4 TP12 TP13 TP14 TP15 TP22 TP23 TP24 TP25 TP32 TP33 TP34 TP35 TP43 TP44 TP45 TP46 TP54 TP55 TP56 TP57: library part CMP-0055139-1, "Test Point, Miniature, White, TH", Color=White, Manufacturer=Keystone, PartNumber=5002, Supplier Part Number 1=36-5002-ND
TP5 TP6 TP7 TP16 TP17 TP18 TP26 TP27 TP28 TP36 TP37 TP39 TP47 TP48 TP50 TP58 TP59 TP61 TP65 TP67 TP69 TP71 TP73 TP75: library part CMP-0055137-1, "Test Point, Miniature, Red, TH", Color=Red, Manufacturer=Keystone, Supplier Part Number 1=36-5000-ND
TP8 TP11 TP19 TP29 TP40 TP51 TP62 TP66 TP68 TP70 TP72 TP74 TP76: library part CMP-0055138-1, "Test Point, Miniature, Black, TH", Color=Black, Manufacturer=Keystone, Supplier Part Number 1=36-5001-ND
TP9 TP10 TP20 TP21 TP30 TP31 TP38 TP41 TP42 TP49 TP52 TP53 TP60 TP63 TP64: library part CMP-0003825-1, "1mm Test Point, SMT", Manufacturer=Any
U1 U2 U3 U4 U5 U6: library part CMP-0093805-2, "Isolated 20-A Adjustable Gate Drive Igbt/Sic Mosfet Gate Driver With Advanced Protection Features For Automotive Applications", Manufacturer="Texas Instruments", Max Supply Voltage=30V, Min Supply Voltage=3V, Nominal Supply Current=6.5-15mA, Operating Temperature Range="-40°C to +150°C"
U7 U8 U9 U10 U11 U12: library part CMP-0078633-2, "70-V PSR Flyback Converter With 100-V, 1.2-A Power Switch and Ultra-Low IQ, NGU0008C (WSON-8)", Alternate Manufacturer="Texas Instruments", Alternate PartNumber=LM5180QNGUTQ1
U13 U14: library part CMP-0092719-1, "NAND Gate IC 4 Channel Schmitt Trigger Input 14-WQFN (3x2.5)", Digikey Part Number=296-SN74HCS00BQARCT-ND, Manufacturer="Texas Instruments", Max Supply Voltage=6V, Min Supply Voltage=2V, Mouser Part Number=595-SN74HCS00BQAR, Nominal Supply Current=0.1uA, Operating Temperature Range="-40°C to +125°C"

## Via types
v1: diameter 15.75, hole 7.87, Top Layer to Bottom Layer, tented both sides, 599 vias
v2: diameter 23.62, hole 11.81, Top Layer to Bottom Layer, tented both sides, 92 vias
v3: diameter 19.68, hole 7.87, Top Layer to Bottom Layer, tented both sides, 28 vias

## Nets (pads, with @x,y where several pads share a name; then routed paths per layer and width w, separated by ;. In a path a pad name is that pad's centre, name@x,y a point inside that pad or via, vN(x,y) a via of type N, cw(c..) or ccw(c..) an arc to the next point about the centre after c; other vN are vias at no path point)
AI1H_U: J17.1 Q7.T1 R33.2 R36.2 TP7.1 | length 2134.7
  Top Layer w20: R33.2@1246.68,1279.58 1248.19,1281.09 R36.2@1284.87,1281.09 ; R36.2@1284.89,1281.11 v1(1284.89,1309.41)
  Signal Layer 2 w20: v1(1284.89,1309.41) 1402.15,1309.41 2015,1922.26 2015,2351.81 J17.1@2120.08,2456.89 2266.1,2602.91 TP7.1@2565,2602.91
AI1H_V: J23.1 Q7.T3 R71.2 R74.2 TP18.1 | length 2040.5
  Top Layer w10: R74.2@2985.22,1292.42 v1(2985.22,1314.07)
  Top Layer w20: R74.2@2985.22,1292.42 2985.36,1292.56 3030.49,1292.56 R71.2@3030.63,1292.7
  Signal Layer 1 w10: v1@2984.78,1314.69 3970.47,2300.38 J23.1@3970.47,2456.89
  Signal Layer 2 w20: TP18.1@3790,2805 3970.47,2624.53 J23.1@3970.47,2456.89
AI1H_W: J6.1 Q7.T5 R109.2 R112.2 TP28.1 | length 2151.3
  Top Layer w12: R112.2@5430,1126.38 cw(c5432.32,1114.6) 5432.88,1126.59 5435.81,1133.38 5439.67,1133.38 5443.32,1137.03 v1(5450.31,1137.03)
  Top Layer w20: R112.2@5430.32,1121.05 5430.32,1086.52 R109.2@5430.65,1086.2
  Signal Layer 2 w12: v1(5450.31,1137.03) 5647.03,1137.03 6255,1745 6255,2061.43 5938.68,2377.76 ; J6.1@5820.87,2456.89 5900,2377.76 5938.68,2377.76 ; TP28.1@6025,2456.89 5945.87,2377.76 5938.68,2377.76
AI1L_U: C102.1 R156.1 R157.2 TP38.1 U4.20 | length 1503.1
  Top Layer w10: U4.20@1056.93,3013.7 1113.58,3013.7 1197.4,2929.88 1341.94,2929.88 1348.75,2923.07 C102.1@1348.75,2919.13
  Top Layer w12: v1(1370.4,2897.78) 1370.4,2919.17
  Top Layer w20: C102.1@1348.75,2919.13 1348.79,2919.17 1370.4,2919.17 R157.2@1393.75,2919.21 R157.2@1393.75,2919.21 ; R156.1@2295,3032.09 v1(2295,3082.5) TP38.1@2295,3134.38
  Signal Layer 2 w12: v1(1370.4,2897.78) 2110.28,2897.78 v1(2295,3082.5)
AI1L_V: C132.1 R199.1 R200.2 TP49.1 U5.20 | length 1482.9
  Top Layer w10: C132.1@2648.62,4173.32 2652.56,4173.32 v1(2673,4193.76) 2728.24,4249 2745.85,4249 2820.63,4323.78 2820.63,4355 U5.20@2823.7,4358.07
  Top Layer w20: TP49.1@2270,3740 2327.91,3682.09 R199.1@2755,3682.09 v1(2755,3719.49) ; R200.2@2648.62,4126.93 C132.1@2648.62,4173.32
  Signal Layer 2 w20: v1(2673,4193.76) 2565,4085.76 2565,3871.07 2716.58,3719.49 v1(2755,3719.49)
AI1L_W: C162.1 R242.1 R243.2 TP60.1 U6.20 | length 1824.5
  Top Layer w12: R243.2@5185.12,4200 5210.71,4200 ; v1(5210.58,4223.41) 5210.58,4200.13 5210.71,4200 ; U6.20@5341.69,4358.07 5339.62,4356 5339.62,4319.97 5219.65,4200 5210.71,4200
  Top Layer w20: TP60.1@4115,3625 v1(4222.09,3517.91) R242.1@4222.09,3437.17 ; C162.1@5185.12,4155 R243.2@5185.12,4200
  Signal Layer 2 w20: v1(4222.09,3517.91) 4470.72,3517.91 5176.22,4223.41 v1(5210.58,4223.41)
ASC_EN_PRI: J1.b12 R22.1 R60.1 R98.1 R134.1 R177.1 R220.1 | length 15586.2
  Top Layer w12: v1@2965,5061.01 v1(2965,5175)
  Top Layer w20: J1.b12@840,4950 v2(840,5010)
  Signal Layer 1 w10: v1(263.96,819.93) 220,863.89 220,1957.51 589.45,2326.96 589.45,2660.59 453.8,2796.24 453.8,3109.09 428.24,3134.65 312.81,3134.65 v1(290.22,3157.24) ; v1(1071.38,305) 1292.64,83.74 2767.91,83.74 ; v1(2767.91,271.38) 2767.91,83.74 ; v1(5091.38,335) 5091.38,285.38 4889.73,83.74 2767.91,83.74
  Signal Layer 1 w12: v2(840,5010) 940,5110 2915,5110 v1(2965,5060)
  Signal Layer 2 w10: v1(263.96,819.93) 263.96,731.44 753.28,242.13 982.73,242.13 1012.25,271.65 1039.59,271.65 1071.38,303.44 v1(1071.38,305)
  Signal Layer 2 w12: v1(290.22,3157.24) 314.49,3181.51 314.49,3984.49 620,4290 620,4752.51 692.49,4825 775,4825 830,4880 830,4997.16 840,5007.16 v2(840,5010) ; v1(2965,5175) 3027.42,5237.42 5292.58,5237.42 v1(5470,5060)
  Bottom Layer w10: v1(290.22,3157.24) R134.1@331.38,3157.24 ; R22.1@1069.76,342.13 1070.57,341.31 1070.57,305.81 v1(1071.38,305) ; v1(2767.91,271.38) 2767.98,271.45 2767.98,306.42 R60.1@2768.05,306.5 ; R98.1@5090,371.38 5090.69,370.69 5090.69,335.69 v1(5091.38,335) ; R220.1@5470,5018.62 v1(5470,5060)
  Bottom Layer w12: R177.1@2965,5018.62 v1(2965,5060)
ASCH_S_EN_U: C14.1 R32.1 R38.2 U1.18 | length 247.5
  Top Layer w10: U1.18@1178.01,1027.68 1181.08,1030.75 1181.08,1063.07 1198.44,1080.43 v1(1225,1080.43) 1226.1,1081.53 1247.66,1081.53 1261.25,1095.12 1278.84,1095.12 C14.1@1283.72,1100
  Top Layer w20: R32.1@1285.16,1005.4 R32.1@1286.38,1006.62 C14.1@1286.38,1097.84
ASCH_S_EN_V: C44.1 R70.1 R76.2 U2.18 | length 251.9
  Top Layer w10: U2.18@2961.6,982.05 2961.6,1027.26 2993.18,1058.84 C44.1@3061.38,1058.84
  Top Layer w12: R70.1@3061.38,965 C44.1@3061.38,1058.84
ASCH_S_EN_W: C74.1 R108.1 R114.2 U3.18 | length 489.4
  Top Layer w12: U3.18@5283.54,992.05 5285.61,994.12 5285.61,1026.82 5299.97,1041.17 5538.34,1041.17 5609.61,1112.44 C74.1@5609.61,1116.38 R108.1@5655,1116.38 R114.2@5700,1116.38
ASCH_SEC_U: C13.1 R29.1 R37.2 U1.19 | length 488.6
  Top Layer w10: U1.19@1154.39,1027.68 1157.46,1030.75 1157.46,1062.51 1234.01,1139.05 1279.57,1139.05 C13.1@1283.72,1143.21 ; v1(1283.72,1123.43) C13.1@1283.72,1143.21 ; C13.1@1286.38,1145.87 C13.1@1283.72,1143.21
  Top Layer w20: C13.1@1286.38,1145.87 R37.2@1286.38,1190 ; R29.1@1416.23,1293.1 1416.23,1288.06 1416.94,1287.35 v1(1416.94,1260.35)
  Signal Layer 2 w10: v1(1283.72,1123.43) 1415.84,1255.55 1415.84,1259.25 v1(1416.94,1260.35)
ASCH_SEC_V: C43.1 R67.1 R75.2 U2.19 | length 292.8
  Top Layer w10: U2.19@2937.97,982.05 2937.97,1030.28 3011.32,1103.62 C43.1@3061.38,1103.62
  Top Layer w12: C43.1@3061.38,1103.62 R67.1@3061.38,1194.4
ASCH_SEC_W: C73.1 R105.1 R113.2 U3.19 | length 403.3
  Top Layer w12: U3.19@5259.92,992.05 5261.99,994.12 5261.99,1028.52 5292.64,1059.17 5463.18,1059.17 5475,1070.99 C73.1@5475,1116.38 R113.2@5520,1116.38 R105.1@5565,1116.38
ASCL_S_EN_U: C104.1 R146.1 R150.2 U4.18 | length 641.1
  Top Layer w10: U4.18@1056.93,2966.46 1101.54,2966.46 1226.55,2841.44 1491.24,2841.44 1504.17,2854.37 1528.19,2854.37 1535,2861.18 R150.2@1535,2919.21
  Top Layer w20: R150.2@1535,2919.21 C104.1@1580,2919.21
ASCL_S_EN_V: C134.1 R189.1 R193.2 U5.18 | length 416.6
  Top Layer w10: C134.1@2648.62,4311.24 C134.1@2655.43,4304.43 ; C134.1@2662.59,4304.43 v1(2674.21,4304.43) 2754.03,4304.43 2773.39,4323.78 2773.39,4355 U5.18@2776.46,4358.07
  Top Layer w20: v1(2513.62,4353.07) 2539.45,4353.07 R189.1@2540,4353.62 ; C134.1@2648.62,4311.24 R193.2@2648.62,4356.5
  Signal Layer 1 w20: v1(2513.62,4353.07) 2625.57,4353.07 v1(2674.21,4304.43)
ASCL_S_EN_W: C164.1 R232.1 R236.2 U6.18 | length 388.8
  Top Layer w12: v1(5054.19,4327.53) 5054.36,4327.7 5075.67,4327.7 R232.1@5075.84,4327.87 ; C164.1@5185.12,4337.19 5189.06,4337.19 5208.83,4317.41 v1(5209.5,4317.41) ; v1@5209.16,4317.08 5217.24,4309 5278.01,4309 5292.38,4323.37 5292.38,4356 U6.18@5294.45,4358.07
  Top Layer w20: C164.1@5185.12,4337.19 R236.2@5185.12,4384.06
  Signal Layer 1 w12: v1(5054.19,4327.53) 5198.37,4327.53 5208.48,4317.41 v1(5209.5,4317.41)
ASCL_SEC_U: C103.1 R143.1 R149.2 U4.19 | length 671.4
  Top Layer w10: U4.19@1056.93,2990.08 1114.71,2990.08 1228.33,2876.46 1427.76,2876.46 1433.61,2882.31 1433.61,2912.83 R149.2@1440,2919.21
  Top Layer w20: R143.1@1413.62,2807.83 v1(1447.24,2807.83) ; R149.2@1440,2919.21 C103.1@1485,2919.21 1483.58,2917.79 v1(1483.58,2875.87)
  Signal Layer 2 w20: v1(1447.24,2807.83) 1483.58,2844.17 v1(1483.58,2875.87)
ASCL_SEC_V: C133.1 R186.1 R192.2 U5.19 | length 454.5
  Top Layer w10: C133.1@2648.62,4264.91 v1(2674.21,4264.91) 2738.13,4264.91 2797.01,4323.78 2797.01,4355 U5.19@2800.08,4358.07
  Top Layer w20: v1(2513.62,4230.47) R186.1@2540,4230.47 ; R192.2@2648.62,4220 C133.1@2648.62,4264.91
  Signal Layer 1 w20: v1(2513.62,4230.47) 2639.78,4230.47 v1(2674.21,4264.91)
ASCL_SEC_W: C163.1 R229.1 R235.2 U6.19 | length 449.7
  Top Layer w12: R229.1@5075.84,4209.78 v1(5075.84,4246.55) ; R235.2@5185.12,4245 5190.93,4250.81 5201.77,4250.81 5201.9,4250.94 v1(5221.61,4250.94) ; C163.1@5185.12,4290.19 5284.52,4290.19 5316,4321.67 5316,4356 U6.19@5318.07,4358.07
  Top Layer w20: R235.2@5185.12,4245 C163.1@5185.12,4290.19
  Signal Layer 1 w12: v1(5075.84,4246.55) 5216.2,4246.55 5220.59,4250.94 v1(5221.61,4250.94)
DesatH_U: C3.1 D2.1 R4.1 TP3.1 U1.23 | length 2631.6
  Top Layer w10: v1(1059.9,985.35) U1.23@1059.9,1027.68
  Top Layer w20: v1(1276.3,1496.69) 1324.9,1496.69 R4.1@1326.71,1498.5 1326.78,1498.43 1326.78,1425.07 D2.1@1326.85,1425
  Signal Layer 2 w10: v1(1059.9,985.35) 1059.9,1003.12 1210.45,1153.67 1283.7,1153.67 2430.03,2300 TP3.1@2580,2300 ; 1232.43,1157.88 1232.43,1452.82 v1(1276.3,1496.69)
  Bottom Layer w12: C3.1@1057.5,1016.85 C3.1@1059.9,1014.45
  Bottom Layer w15: v1(1059.9,985.35) C3.1@1059.9,1014.45
DesatH_V: C33.1 D8.1 R42.1 TP14.1 U2.23 | length 2311.3
  Top Layer w10: U2.23@2843.49,982.05 2843.95,981.58 2843.95,930.46 v1(2844.41,930)
  Top Layer w20: v1(2460,1265) 2516.79,1265 R42.1@2518.44,1263.36 ; R42.1@2520.18,1261.61 2520.18,1262.6 2572.46,1314.88 2577.05,1314.88 D8.1@2578.86,1316.69
  Signal Layer 1 w20: v1(2460,1265) 2460,1815 3000,2355 TP14.1@3000,2425
  Signal Layer 2 w20: v1(2460,1265) 2420,1225 2420,1109.37 2555.31,974.06 2825.92,974.06 2844.41,955.56 v1(2844.41,930)
  Bottom Layer w15: v1(2844.41,930) C33.1@2844.41,972.24
  Bottom Layer w20: C33.1@2839.27,974.06 2842.6,974.06 C33.1@2844.41,972.24
DesatH_W: C63.1 D14.1 R80.1 TP24.1 U3.23 | length 2417.2
  Top Layer w10: v1(5165.43,949.72) U3.23@5165.43,992.05
  Top Layer w20: v1(5048,1270) 5074.88,1296.88 D14.1@5074.88,1480 5152.87,1557.99 5152.87,1561.3 5161.57,1570 R80.1@5162.56,1570
  Signal Layer 2 w10: 5077.83,1270 5077.83,1173.98 5165.43,1086.38 v1(5165.43,949.72)
  Signal Layer 2 w12: v1(5048,1270) 5077.83,1270 5301,1270 5361,1210 5585,1210 5945.87,1570.87 5945.87,1860.87 6080,1995 TP24.1@6170,1995
  Bottom Layer w10: C63.1@5155.79,972.22 5159.73,972.22 C63.1@5166.54,965.41
  Bottom Layer w15: v1(5165.43,949.72) 5165.58,949.87 C63.1@5165.58,964.45
DesatL_U: C93.1 D20.1 R118.1 TP34.1 U4.23 | length 1953.1
  Top Layer w12: v1(1009.61,3085.28) 1009.97,3084.93 1051.57,3084.93 U4.23@1051.93,3084.57
  Top Layer w20: R118.1@1645,2841.5 1645,2897.78 1631.08,2911.69 D20.1@1715,2911.69 1716.81,2913.5 1739.32,2913.5 v1(1745.5,2919.68)
  Signal Layer 2 w12: 1063.33,3051.38 1494.69,3051.38 TP34.1@1805,3361.69
  Signal Layer 2 w20: v1(1009.61,3085.28) 1029.42,3085.28 1063.33,3051.38 1181.44,2933.27 1731.91,2933.27 v1(1745.5,2919.68)
  Bottom Layer w20: v1(1009.61,3085.28) 1010.17,3085.85 1044.92,3085.85 1046.73,3087.66 C93.1@1046.73,3091.59
DesatL_V: C123.1 D26.1 R161.1 TP45.1 U5.23 | length 934.2
  Top Layer w10: TP45.1@2460,3950 2507.1,3997.1 v1@2627.66,3997.1 ; v1(2629.78,3997.34) 2658.19,3968.94 2682.76,3968.94 D26.1@2685,3966.69 2700,3951.69 R161.1@2700,3891.5 ; v1(2894.41,4400.39) 2894.49,4400.31 2894.49,4353.15 U5.23@2894.57,4353.07
  Signal Layer 2 w10: v1(2629.78,3997.34) 2629.78,4041.95 2894.41,4306.58 v1(2894.41,4400.39)
  Bottom Layer w10: C123.1@2902.39,4370.02 C123.1@2906.33,4370.02
  Bottom Layer w12: v1(2894.41,4400.39) 2894.41,4399.38 v1@2896.58,4397.21 ; C123.1@2896.58,4375.83 C123.1@2902.39,4370.02
  Bottom Layer w15: C123.1@2896.58,4375.83 v1@2896.58,4397.21
DesatL_W: C153.1 D32.1 R204.1 TP56.1 U6.23 | length 1450.1
  Top Layer w10: U6.23@5412.56,4358.07 v1(5412.56,4400.39)
  Signal Layer 2 w20: TP56.1@4697.97,3520 4697.97,3628.3 5044.67,3975 5286.64,3975 5457.73,4146.09 5457.73,4245.02 5412.56,4290.19 v1(5412.56,4400.39)
  Bottom Layer w20: v1(5412.56,4400.39) 5412.56,4365.89 5417.7,4360.75 5417.7,4356.81 5419.51,4355 C153.1@5423.44,4355
  other v1: 5171.5,3975
GD0: R14.1 R52.1 R90.1 R128.1 R171.1 R214.1 U13.8 | length 15314.3
  Top Layer w10: v1(1829.57,4530) U13.8@1829.57,4569.88
  Signal Layer 1 w10: v1(290.22,3299.06) 290.22,3312.01 ; v1(365,762.68) 365,830 285,910 285,1941.68 637.17,2293.85 637.17,2684.85 503.31,2818.71 503.31,3265.8 457.09,3312.01 290.22,3312.01 ; v1(745,4245) 545,4245 261.81,3961.81 261.81,3327.47 277.26,3312.01 290.22,3312.01 ; v1(925,4245) 1017.5,4337.5 1017.5,4592.5 1085.29,4660.29 1312.76,4660.29 1454.95,4518.09 1732,4518.09 1743.91,4530 v1(1829.57,4530) 2106.18,4530 2549.53,4973.35 3100,4973.35 ; v1(932.51,305) 933.1,305 999.17,371.06 1316.3,371.06 1368.97,318.4 1368.97,296.03 1395,270 1530.54,270 1640.54,160 2521.67,160 v1(2633.05,271.38) 2633.05,318.31 2665.97,351.22 2859.62,351.22 2924.62,416.22 3687.3,416.22 3804.52,299 4919,299 v1(4955,335) ; v1(3100,5060) 3100,4973.35 ; v1(5605,5060) 5508.54,4963.54 4951.29,4963.54 4830.62,4842.88 3513.27,4842.88 3382.81,4973.35 3100,4973.35
  Signal Layer 2 w10: v1(365,762.68) 365,720 743.98,341.02 896.49,341.02 v1(932.51,305) ; v1(745,4245) v1(925,4245)
  Bottom Layer w10: v1(290.22,3299.06) 290.69,3299.53 330.91,3299.53 R128.1@331.38,3300 ; v1(932.51,305) R14.1@932.51,342.13 ; v1(2633.05,271.38) R52.1@2633.05,306.5 ; v1(4955,335) R90.1@4955,371.38 ; R214.1@5605,5018.62 v1(5605,5060)
  Bottom Layer w12: R171.1@3100,5018.62 v1(3100,5060)
GD1: R15.1 R53.1 R91.1 R129.1 R172.1 R215.1 U13.3 U13.4 | length 15522.3
  Top Layer w12: v1(1740,4635) 1774.45,4635 ; U13.4@1774.45,4627.1 1774.45,4635 ; U13.3@1774.45,4640.21 1774.45,4635 ; 1775,4635 1774.45,4635
  Signal Layer 1 w10: v1(290.22,3251.38) 311.49,3230.1 472.02,3230.1 486.46,3215.67 486.46,2813.06 621.26,2678.26 621.26,2306.26 263.96,1948.96 263.96,904.54 340,828.5 v1(340,762.68) ; v1(976.41,305) 1015.5,344.09 1089.76,344.09 1213.85,220 1530.21,220 1626.24,123.98 2547.24,123.98 2676.95,253.69 2676.95,270.28 v1(2678.05,271.38) 2720.89,314.21 2791.54,314.21 2986.65,119.09 4784.09,119.09 v1(5000,335) ; v1(3055,5060) 3083.02,5088.02 3106.42,5088.02 3121.22,5073.22 3121.22,5046.3 3136.01,5031.5 3350.51,5031.5 3520.32,4861.69 4823.36,4861.69 4942.89,4981.22 5481.22,4981.22 v1(5560,5060)
  Signal Layer 1 w12: v1(290.22,3251.38) 240,3301.6 240,3970 560,4290 v1(780,4290) ; v1(925,4290) 995,4360 995,4594.36 1080.76,4680.12 1316.84,4680.12 1461.96,4535 1725,4535 1782.5,4592.5 ; v1(1740,4635) 1782.5,4592.5 ; v1(3055,5060) 2990,4995 2535.3,4995 2090.3,4550 1825,4550 1782.5,4592.5
  Signal Layer 2 w10: v1@340,765 v1(340,762.68) 340,709.37 772.71,276.66 948.07,276.66 v1(976.41,305)
  Signal Layer 2 w12: v1(780,4290) v1(925,4290)
  Bottom Layer w10: v1(290.22,3251.38) 290.4,3251.55 331.2,3251.55 R129.1@331.38,3251.73 ; v1(976.41,305) 976.96,305.55 976.96,341.57 R15.1@977.51,342.13 ; v1(2678.05,271.38) R53.1@2678.05,306.5 ; v1(5000,335) R91.1@5000,373.35 ; R215.1@5560,5018.62 v1(5560,5060)
  Bottom Layer w12: R172.1@3055,5018.62 v1(3055,5060)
